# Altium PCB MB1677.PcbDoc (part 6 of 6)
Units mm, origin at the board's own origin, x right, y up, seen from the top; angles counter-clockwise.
Board outline 78 x 105 mm, 6 copper layers (Top Layer, Signal Layer 1, Signal Layer 2, Signal Layer 3, Signal Layer 4, Bottom Layer), stack 1.574 mm thick; 404 components, 325 nets, 1691 pads, 961 vias.
Unrouted connection lines stored in the file: 9.
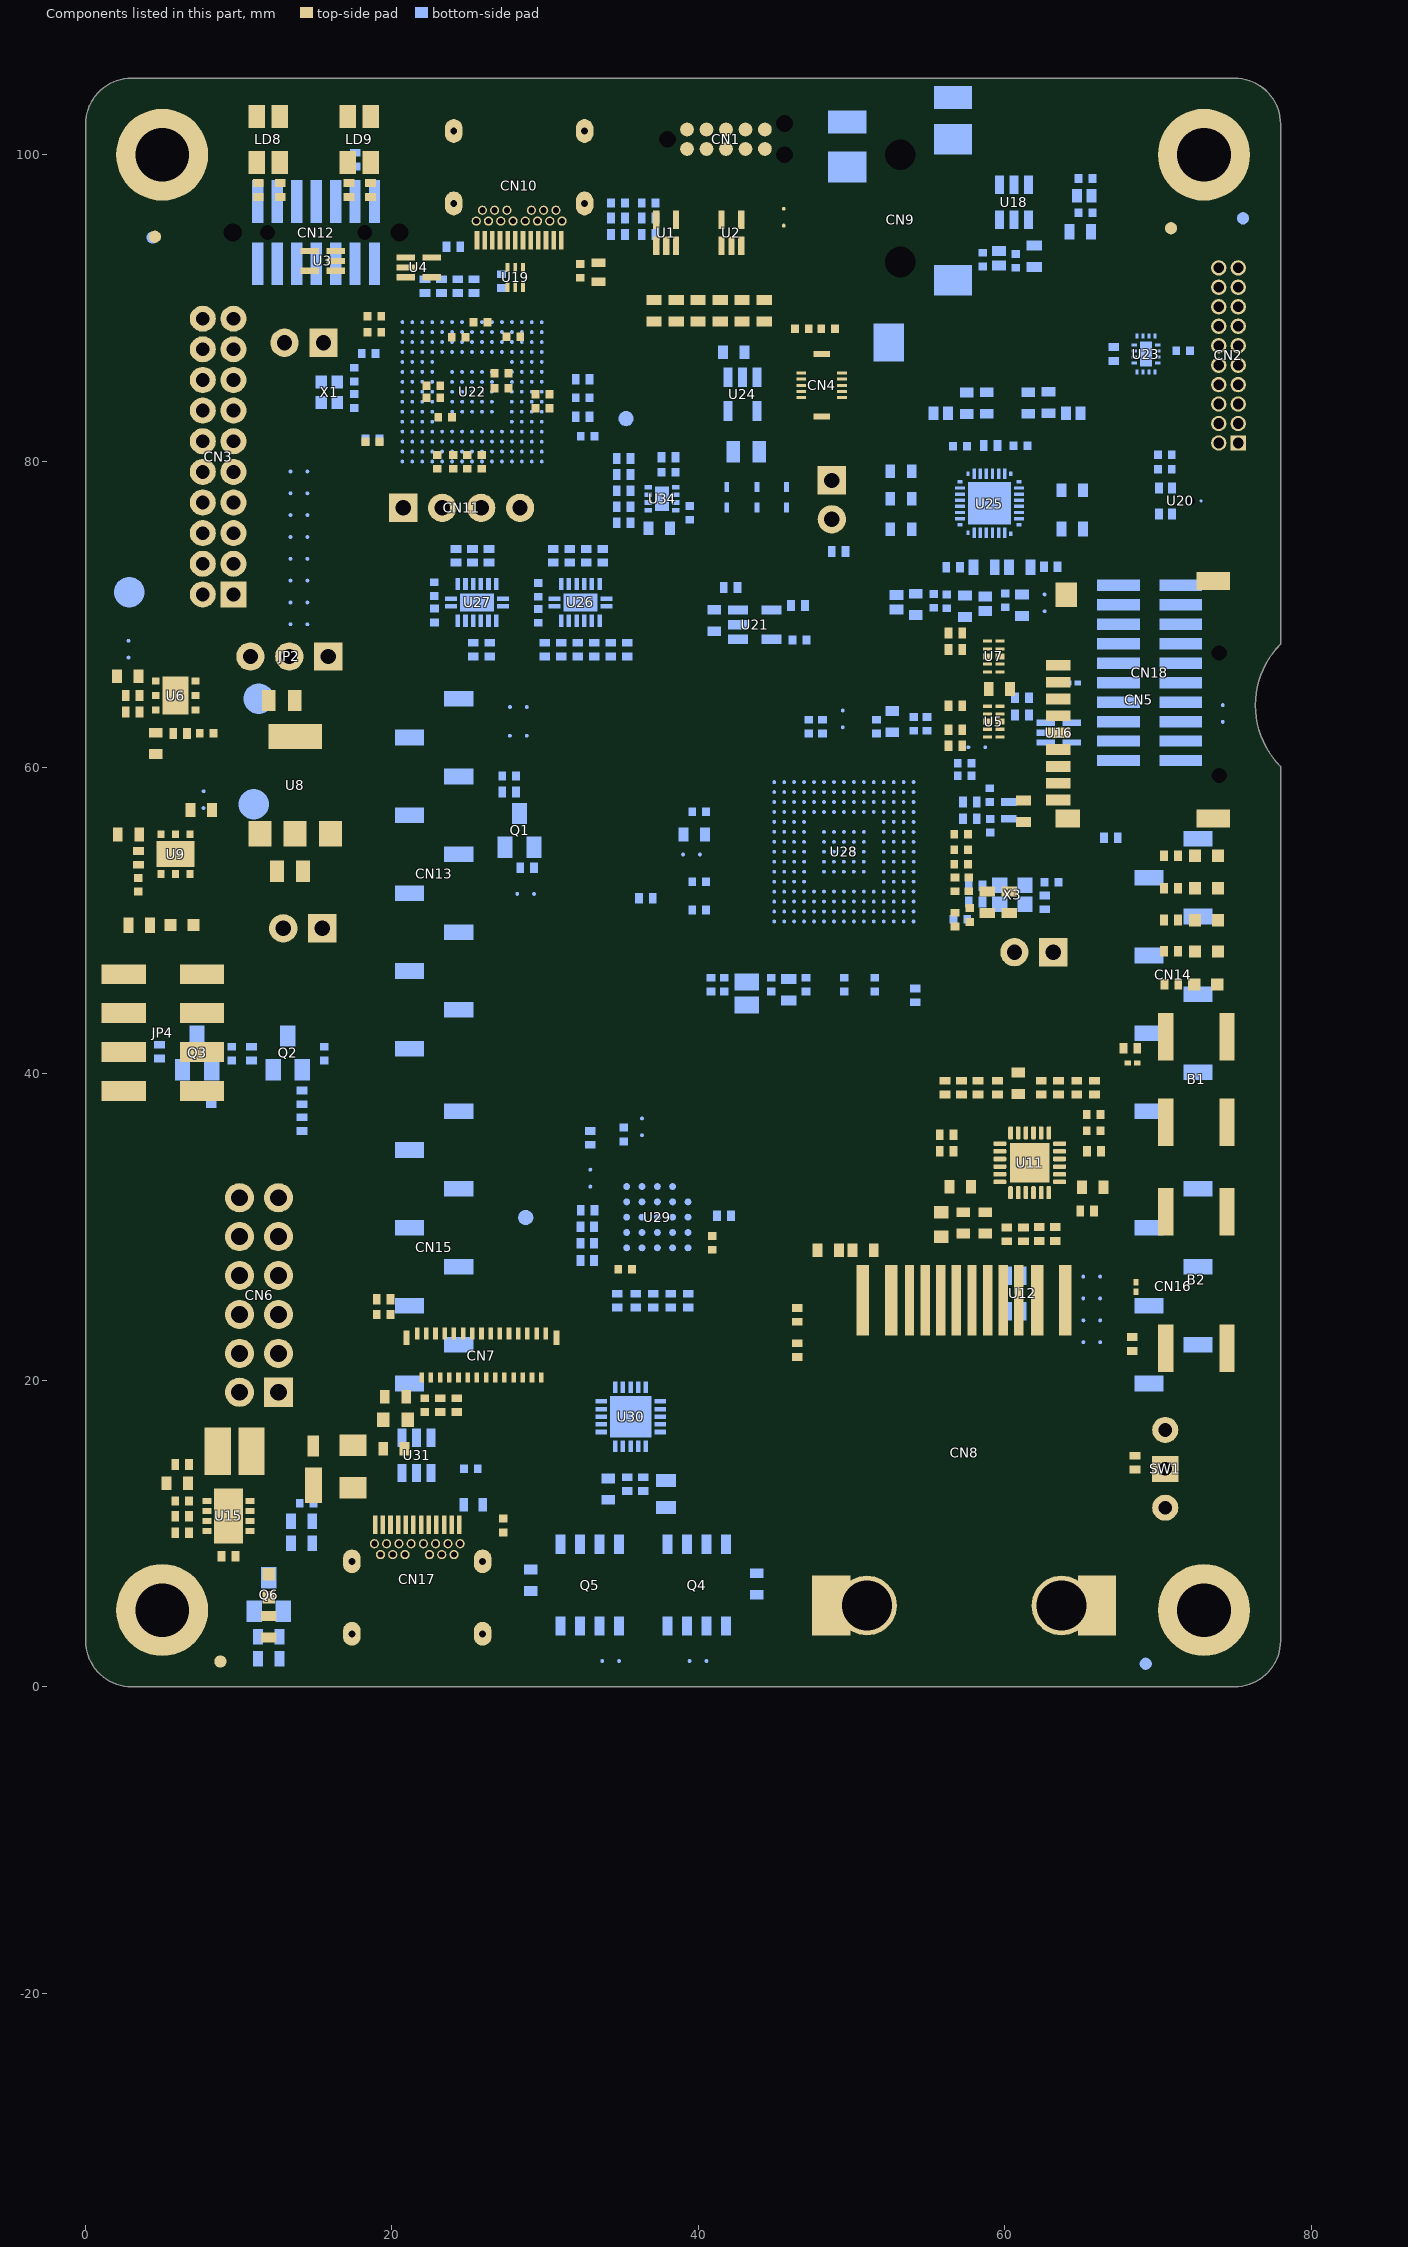
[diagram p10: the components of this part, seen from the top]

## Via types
v1: diameter 0.55, hole 0.35, Top Layer to Bottom Layer, tented both sides, 748 vias
v2: diameter 0.4, hole 0.2, Top Layer to Bottom Layer, tented both sides, 203 vias
v3: diameter 0.6, hole 0.3, Top Layer to Bottom Layer, tented both sides, 9 vias
v4: diameter 0.55, hole 0.33, Top Layer to Bottom Layer, tented both sides, 1 vias

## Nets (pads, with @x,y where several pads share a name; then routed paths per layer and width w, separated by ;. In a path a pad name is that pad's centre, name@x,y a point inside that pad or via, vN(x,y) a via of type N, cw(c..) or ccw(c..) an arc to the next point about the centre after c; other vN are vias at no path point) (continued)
pads on no net: CN1.7 CN1.11 CN1.12 CN1.13 CN2.3 CN2.8 CN2.9 CN2.11 CN2.13 CN2.14 CN2.15 CN2.16 CN2.17 CN2.18 CN4.MT1 CN4.MT2 CN5.NPTH1 CN5.NPTH2 CN6.9 CN6.10 CN7.MT1 CN7.MT2 CN8.9 CN9.5 CN9.7 CN9.MT1 CN9.MT2 CN10.A2 CN10.A3 CN10.A8 CN10.A10 CN10.A11 CN10.B2 CN10.B3 CN10.B8 CN10.B10 CN10.B11 CN12.0 CN12.1 CN12.2 CN17.A2 CN17.A3 CN17.A8 CN17.A10 CN17.A11 CN17.B2 CN17.B3 CN17.B8 CN17.B10 CN17.B11 CN18.7 Designator90.1 Designator91.1 Designator92.1 Designator93.1 Designator94.1 Designator95.1 U1.4 U1.5 U4.4 U7.4 U7.5 U7.6 U7.7 U9.3 U11.4 U15.5 U19.4 U20.6 U22.A1 U22.A2 U22.A3 U22.A4 U22.A5 U22.A8 U22.A9 U22.A11 U22.A12 U22.A13 U22.B1 U22.B2 U22.B3 U22.B4 U22.B5 U22.B6 U22.B7 U22.B8 U22.B9 U22.B10 U22.B11 U22.B12 U22.B14 U22.B15 U22.C2 U22.C3 U22.C4 U22.C12 U22.C13 U22.C14 U22.C15 U22.D1 U22.D2 U22.D3 U22.D11 U22.D13 U22.D14 U22.E1 U22.E2 U22.E3 U22.E4 U22.E12 U22.E13 U22.E14 U22.E15 U22.F1 U22.F4 U22.F14 U22.G4 U22.G14 U22.G15 U22.H2 U22.H3 U22.H4 U22.H14 U22.J2 U22.J3 U22.J4 U22.K1 U22.K2 U22.K3 U22.K12 U22.K13 U22.K14 U22.K15 U22.L1 U22.L12 U22.L13 U22.L14 U22.L15 U22.M2 U22.M3 U22.M4 U22.M7 U22.M12 U22.M13 U22.M14 U22.M15 U22.N2 U22.N4 U22.N6 U22.N7 U22.N11 U22.N13 U22.N14 U22.N15 U22.P2 U22.P4 U22.P5 U22.P6 U22.P7 U22.P8 U22.P9 U22.P10 U22.P11 U22.P12 U22.P13 U22.P14 U22.P15 U22.R2 U22.R6 U22.R7 U22.R8 U22.R9 U22.R10 U22.R11 U22.R12 U22.R13 U23.7 U23.8 U23.9 U23.12 U23.13 U23.14 U23.17 U24.4 U25.16 U25.17 U25.18 U25.24 U25.25 U25.26 U27.3 U27.14 U28.A10 U28.C14 U28.G3 U28.H3 U28.J2 U28.K15 U28.N8 U29.A2 U29.A3 U29.B1 U29.B5 U31.5

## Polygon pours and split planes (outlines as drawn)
GND on Bottom Layer "GND" (solid, remove dead copper, pour order 57): 0.525,107 78.425,107 80.375,105.05 80.375,-0.475 78.4,-2.45 0.025,-2.45 -2.975,0.55 -2.975,103.5
no net on Bottom Layer "NO_FT" (solid, remove dead copper, pour order 8): 48.597,17.325 66.325,17.325 66.325,0 48.697,0 48.597,0.004
5V_STLK on Bottom Layer "5V_STLK" (solid, remove dead copper, pour order 52): 36.475,76.275 36.08,75.88 36.08,75.375 35.85,75.145 35.85,74.65 36,74.5 37.21,74.5 37.347,74.638 37.347,76.004 37.077,76.275
5V_VIN on Bottom Layer "5V_VIN" (solid, pour order 50): 3.6,39.5 4.125,40.025 4.125,41.405 3.675,41.855 3.675,43.734 4.4,44.459 11.159,44.459 14.27,47.57 14.27,50.28 13.469,51.081 12.106,51.081 8.525,47.5 3.45,47.5 1,45.05 1,39.95 1.45,39.5
VBUS_STLK on Bottom Layer "VBUS_STLK" (solid, pour order 47): 42.625,75.075 36.775,69.225 36.775,62.412 36.25,61.888 35.637,61.888 34.85,62.675 34.85,70.565 41.56,77.275 42.3,77.275 42.625,76.95
NetC95_1 on Bottom Layer "NO_FT" (solid, pour order 1): 53.05,60.3 52.625,59.875 52.625,59.05 52.75,59.05 52.875,59.05 52.875,59.425 53.4,59.95
NetC80_2 on Bottom Layer "NO_FT" (solid, pour order 18): 42.7,84.725 43.325,85.35 43.325,86.301 43.479,86.455 44.632,86.455 44.75,86.337 44.75,80.225 45.375,79.6 46.05,79.6 46.55,79.1 46.55,77.975 46.225,77.65 41.475,77.65 41.05,78.075 41.05,79.5 41.225,79.675 42.775,79.675 43.4,80.3 43.4,83.85 43.2,84.05 42.525,84.05 42.4,83.925 42.4,82.525 42.125,82.25 41.275,82.25 40.975,82.55 40.975,84.2 41.5,84.725
NetC125_1 on Bottom Layer "NO_FT" (solid, pour order 6): 38.7,10.975 40,12.275 43.3,12.275 44.9,10.675 44.9,7.375 44.45,6.925 43.4,6.925 43.275,7.05 43.275,8.2 42.95,8.525 41.35,8.525 41.1,8.775 41.1,10.5 40.775,10.825 40.375,10.825 39.95,10.4 39.95,8.75 39.725,8.525 38.95,8.525 38.7,8.775
5V_UCPD on Bottom Layer "NO_FT" (solid, pour order 42): 33.68,2.325 34.075,1.93 34.075,1.43 33.17,0.525 31.65,0.525 31.125,1.05 31.125,2.05 31.4,2.325
5V on Bottom Layer "NO_FT" (solid, pour order 41): 39.455,2.25 39.525,2.18 39.525,1.18 38.87,0.525 37.55,0.525 36.85,1.225 36.85,2.15 36.95,2.25
VIN on Bottom Layer "VIN" (solid, pour order 39): 16.925,54.6 16.225,55.3 15.075,55.3 14.05,54.275 14.05,49.875 15.075,48.85 15.75,48.85 16.925,50.025
VIN on Bottom Layer "NO_FT" (solid, pour order 36): 67.275,41.025 66.55,41.025 66.05,40.525 66.05,38.075 66.225,37.9 67.125,37.9 67.825,38.6 67.825,40.475 67.725,40.575
NetC22_2 on Bottom Layer "NO_FT" (solid, pour order 16): 4.008,67.275 4.197,67.085 4.197,65.622 3.95,65.375 2.55,65.375 2.15,65.775 2.15,67.125 2.3,67.275
3V3 on Bottom Layer "NO_FT" (solid, pour order 13): 7.2,58.7 7.2,59.675 7.825,60.3 9.5,60.3 9.85,59.95 9.85,58.25 9.3,57.7 8.2,57.7
NetC27_2 on Bottom Layer "NO_FT" (solid, pour order 12): 5.65,56.65 5.9,56.4 8.325,56.4 8.45,56.525 8.45,57.2 8.2,57.45 7.025,57.45 6.425,58.05 5.8,58.05 5.65,57.9
NetC124_1 on Bottom Layer "NO_FT" (solid, pour order 7): 35.425,10.525 34.35,11.6 29.475,11.6 28.05,10.175 28.05,7.15 28.25,6.95 29.2,6.95 30.775,8.525 35.2,8.525 35.425,8.75
UCPD_SOURCE on Bottom Layer "NO_FT" (solid, pour order 5): 39.9,7.9 40.225,8.225 42.675,8.225 43.025,7.875 43.025,6.9 43.225,6.7 43.23,6.705 44.47,6.705 44.6,6.575 44.6,3.325 42.275,1 40.45,1 40.35,1.1 40.35,2.625 39.9,3.075
UCPD_SNK03 on Bottom Layer "NO_FT" (solid, pour order 4): 33,7.8 33.15,7.95 35.7,7.95 36.1,7.55 36.1,1.45 35.675,1.025 34.905,1.025 34.6,1.33 34.6,2 34.42,2.18 34.075,2.18 33,3.255
NetC124_2 on Bottom Layer "NO_FT" (solid, pour order 2): 29.05,6.955 29.205,6.955 30.775,8.525 39.575,8.525 39.825,8.275 39.825,3.075 39.55,2.8 37.075,2.8 36.575,3.3 36.575,7.325 35.85,8.05 33.125,8.05 32.925,7.85 32.925,3.125 32.5,2.7 29.35,2.7 27.925,4.125 27.925,6.625 28.25,6.95 28.775,6.95
NetC95_1 on Bottom Layer "NO_FT" (solid, pour order 0): 44.725,48.85 45.475,49.6 45.475,49.95 45.6,50.025 45.725,49.95 45.725,49.15 45.075,48.5
VDD on Signal Layer 3 "VDD" (solid, remove dead copper, pour order 60): 0.525,107 78.425,107 80.375,105.05 80.375,-0.475 78.4,-2.45 0.025,-2.45 -2.975,0.55 -2.975,103.5
1V8 on Signal Layer 3 "1V8" (solid, pour order 19): 25.525,73.325 27.65,71.2 30.825,71.2 31.6,71.95 49.25,71.95 59.1,81.8 63.4,81.8 63.725,81.475 63.725,79.475 57.425,73.175 55.05,73.175 51.3,69.425 12.75,69.425 12.1,68.775 12.1,66.425 11.375,65.7 3.735,65.7 2.942,66.492 2.5,66.935 2.5,69.825 3,70.325 5.375,70.325 6.9,68.8 9.625,68.8 14.15,73.325
3V3_STLK on Signal Layer 3 "3V3_STLK" (solid, remove dead copper, pour order 20): 24.625,89.925 26.825,89.925 30.7,86.05 33.4,86.05 37.3,89.95 39.15,89.95 41.4,87.7 41.4,83.05 44.125,80.325 49.375,80.325 50.675,79.025 50.675,73.775 49.025,72.125 33.717,72.125 31.97,73.872 31.005,73.872 27.245,73.872 25.842,75.275 19.7,75.275 18.9,76.075 18.9,80.45 18.425,80.925 17.2,80.925 16.775,81.35 16.775,84.95 19.2,87.375 19.2,89.4 19.725,89.925
5V on Signal Layer 3 "5V" (solid, pour order 37): 13.725,6.675 34.3,6.675 43.4,6.675 52.995,16.27 74.205,16.27 76.55,13.925 76.55,12.85 75.9,12.2 51.875,12.2 40.2,0.525 12.525,0.525 12.525,5.475
3V3_LCD on Signal Layer 3 "3V3_LCD" (solid, pour order 33): 22.008,96.6 18.208,100.4 11.925,100.4 11.275,99.75 11.275,98.15 6.275,93.15 1.775,93.15 1.444,92.819 1.444,44.731 2.95,43.225 9.55,43.225 10.075,42.7 10.075,41.75 9.925,41.6 1.775,41.6 0.5,42.875 0.5,93.35 1.8,94.65 5.425,94.65 9.2,98.425 9.2,100.325 10.9,102.025 20.5,102.025 24.1,98.425 27.875,94.65 44.475,94.65 48.535,90.59 48.535,88.953 48.359,88.778 47.788,88.778 47.625,88.94 47.625,89.725 45.35,92 26.608,92
VBUSC on Signal Layer 3 "VBUSC" (solid, pour order 23): 14.575,6.925 25.425,6.925 25.425,9.825 27.175,11.575 36.6,11.575 36.975,11.95 36.975,15.15 37.725,15.9 38.325,15.9 38.8,16.375 38.8,16.95 38.5,17.25 37.2,17.25 33.625,13.675 24.766,13.675 23.118,12.028 14.028,12.028 10.475,8.475 10.475,4.775 9.55,3.85 9.55,0.5 12.275,0.5 12.275,5.658 13.542,6.925
VBUS_STLK on Signal Layer 3 "VBUS_STLK" (solid, pour order 49): 28.6,41.9 30.425,41.9 33.667,45.142 35.91,45.142 36.342,45.142 36.848,44.637 37.188,44.637 38.2,43.624 38.2,38.5 19.525,38.5 19.025,38 5.725,38 4.644,36.919 3.448,36.919 3.275,37.092 3.275,39.015 3.939,39.679 10.929,39.679 13.15,41.9
5V_UCPD on Signal Layer 3 "5V_UCPD" (solid, pour order 40): 32.625,47.225 30.6,45.2 4.3,45.2 3.925,45.575 3.35,45.575 3.075,45.3 3.075,44.501 4.226,43.35 15.7,43.35 16.975,42.075 30.075,42.075 33.142,45.142 36.342,45.142 36.848,44.637 37.188,44.637 37.465,44.359 37.465,43.985 37.725,43.725 38,43.725 38.575,44.3 38.575,45.1 36.45,47.225
5V on Signal Layer 3 "5V" (solid, remove dead copper, pour order 59): 13.577,37.75 14.576,36.751 15.267,36.751 15.465,36.553 15.465,34.14 14.55,33.225 2.575,33.225 1.925,33.875 1.925,35.8 2.678,36.553 4.778,36.553 5.975,37.75
5V_STLK on Signal Layer 3 "5V_STLK" (solid, remove dead copper, pour order 54): 30.708,45.933 30.708,47.717 30.325,48.1 4.25,48.1 3.75,47.6 3.75,46.183 4.483,45.45 30.225,45.45
VIN on Signal Layer 3 "VIN" (solid, pour order 35): 63.075,37.65 66.5,41.075 67.325,41.075 67.45,40.95 67.45,38.31 67.103,37.963 65.828,37.963 63.865,36 52.2,36 48.825,32.625 43.35,32.625 38.5,37.475 38.5,45.475 36.5,47.475 31.084,47.475 30.359,48.2 18.55,48.2 14.75,52 14.75,53.885 15.915,55.05 19.5,55.05 24.65,49.9 38.625,49.9 40.609,47.916 40.609,38.616 43.597,35.628 47.112,35.628 50.309,38.825 59.05,38.825 60.225,37.65
VDD_MCU on Signal Layer 3 "VDD_MCU" (solid, pour order 45): 49.137,65.862 49.137,64.137 47.65,62.65 43.875,62.65 40.25,59.025 40.25,50.6 41.3,49.55 41.3,47.1 44.75,43.65 48.675,43.65 51.375,46.35 52.75,46.35 53.775,47.375 53.775,50.65 54.725,51.6 58,51.6 58.275,51.325 58.275,47.475 59.55,46.2 61.45,46.2 61.975,46.725 61.975,50.475 59.425,53.025 59.425,60.2 59.825,60.6 59.825,61.25 58.3,62.775 55.9,62.775 55.225,63.45 55.225,65.45 54.6,66.075 49.35,66.075
NetC40_1 on Signal Layer 3 "NO_FT" (solid, pour order 9): 62.575,32.15 63.25,32.825 64.05,32.825 64.625,32.25 64.625,28.45 62.85,26.675 45.875,26.675 45.625,26.925 45.625,27.6 47.05,29.025 57.1,29.025 58.975,30.9 58.975,31.925 59.2,32.15
NetC95_1 on Signal Layer 3 "NO_FT" (solid, pour order 24): 46.05,49.4 45.525,49.925 41.425,49.925 40.75,50.6 40.75,59.05 44.05,62.35 52.875,62.35 53.225,62 53.225,60.774 52.591,60.14 52.591,59.859 53.1,59.35 53.6,59.35 54.65,60.4 54.65,62.275 53.367,63.558 43.683,63.558 39.4,59.275 39.4,49.95 41.05,48.3 45.775,48.3 46.05,48.575
NetC124_2 on Signal Layer 3 "NO_FT" (solid, pour order 3): 37.5,11.6 35.975,10.075 35.975,7.825 36.225,7.575 37.85,7.575 38.4,8.125 38.4,14.775 38.225,14.95 37.625,14.95 37.5,14.825
GND on Top Layer "GND" (solid, remove dead copper, pour order 43): 0.525,107 78.425,107 80.375,105.05 80.375,-0.475 78.4,-2.45 0.025,-2.45 -2.975,0.55 -2.975,103.5
5V on Top Layer "NO_FT" (solid, pour order 26): 5.425,46.5 4.425,47.5 2.625,47.5 1.4,48.725 1.4,50.175 1.9,50.675 3.175,50.675 3.675,50.175 3.675,48.625 4.1,48.2 9.725,48.2 11.125,46.8 11.125,36.05 10.625,35.55 6,35.55 5.425,36.125
5V_VIN on Top Layer "NO_FT" (solid, pour order 31): 0.85,42.275 0.85,40.024 1.149,39.725 3.625,39.725 4.15,40.25 4.15,42.275
VIN on Top Layer "NO_FT" (solid, pour order 25): 15,54.95 14.275,54.225 13.8,54.225 13.35,53.775 13.35,52.275 13.825,51.8 15.75,51.8 16.2,52.25 16.2,53.825 17.2,54.825 17.2,56.425 16.8,56.825 15.3,56.825 15,56.525
NetC22_2 on Top Layer "NO_FT" (solid, pour order 15): 4.95,66.325 4,67.275 3.075,67.275 2.5,66.7 2.5,65.625 2.975,65.15 4.775,65.15 4.95,65.325
3V3 on Top Layer "NO_FT" (solid, pour order 14): 2.575,62.625 2.45,62.5 2.45,61.75 2.7,61.5 5.875,61.5 6.175,61.8 6.175,62.75 5.75,63.175 5.25,63.175 4.95,63.475 4.95,64.05 4.8,64.2 4.2,64.2 4,63.975 4,62.725 3.9,62.625
NetC27_2 on Top Layer "NO_FT" (solid, pour order 11): 5.525,57.725 5.725,57.925 6.85,57.925 7.55,57.225 7.55,55.725 7.05,55.225 5.725,55.225 5.525,55.425
5V on Top Layer "NO_FT" (solid, pour order 10): 2.675,56.7 2.875,56.9 5.025,56.9 5.45,56.475 5.45,55.5 5.175,55.225 4.625,55.225 4.075,54.675 4.075,54.15 4.025,54.1 2.95,54.1 2.675,54.375
GND on Signal Layer 2 "GND" (solid, remove dead copper, pour order 58): 0.525,107 78.425,107 80.375,105.05 80.375,-0.475 78.4,-2.45 0.025,-2.45 -2.975,0.55 -2.975,103.5
VBUS_STLK on Signal Layer 2 "VBUS_STLK" (solid, pour order 46): 25.021,96.85 25.021,97.521 26,98.5 34.175,98.5 36.275,96.4 37.45,95.225 37.45,93.875 43.55,87.775 43.55,76.55 46.625,73.475 46.625,68.915 46.36,68.65 45.075,68.65 44.275,69.45 44.275,71.325 41.025,74.575 39.997,75.603 39.997,83.253 37.475,85.775 37.475,88.975 35.45,91 33.5,91 31.875,92.625 26.675,92.625 25.021,94.279
5V_UCPD on Signal Layer 2 "5V_UCPD" (solid, pour order 51): 35.95,45.95 36.575,46.575 37.382,46.575 39.625,44.284 39.625,31.955 32.775,25.105 32.775,13.95 33.425,13.3 33.425,0.942 33.008,0.525 31.925,0.525 30.55,1.9 30.55,28.025 35.95,33.425
5V on Signal Layer 2 "5V" (solid, pour order 29): 3.15,60.125 4,59.275 4,44.224 4.65,43.574 4.65,15.1 13.263,6.487 14.603,6.487 14.783,6.308 14.783,5.208 14.375,4.8 9.425,4.8 1.025,13.2 1.025,92.2 1.85,93.025 5.575,93.025 5.975,92.625 5.975,78.875 3.15,76.05
3V3_STLK on Signal Layer 2 "3V3_STLK" (solid, remove dead copper, pour order 53): 21.4,88.35 21.5,88.45 21.5,90.9 18.875,93.525 18,93.525 17.7,93.825 17.7,103.675 17.308,104.067 11.023,104.067 10.825,103.869 10.825,103.325 12.75,101.4 14.725,101.4 15.825,100.3 15.825,93.3 18.4,90.725 19.175,90.725 19.175,88.525 19.35,88.35
VBUS_STLK on Signal Layer 2 "VBUS_STLK" (solid, pour order 48): 34.187,64.062 34.187,60.591 32.65,59.054 32.65,58.602 32.65,54.679 31.85,53.879 31.85,45.85 34.712,42.987 36.263,42.988 37.025,43.75 37.025,44.125 33.825,47.325 33.825,53.65 34.8,54.625 34.8,57.925 36.8,59.925 36.8,64.75 36.45,65.1 35.225,65.1
5V_STLK on Signal Layer 2 "5V_STLK" (solid, remove dead copper, pour order 56): 33.925,64.233 33.925,60.7 32.475,59.25 32.475,58.879 32.475,54.975 31.525,54.025 31.525,46.75 30.7,45.925 28.307,45.925 27.8,46.432 27.8,59.65 30.316,62.166 30.316,64.991 34.3,68.975 34.3,75.45 34.7,75.85 37.15,75.85 37.6,75.4 37.6,74.125 41.025,70.7 41.025,69 37.425,65.4 35.092,65.4
5V on Signal Layer 2 "5V" (solid, pour order 38): 73.775,45.825 73.775,42.875 74.65,42 74.65,12.95 75.225,12.375 76.125,12.375 76.875,13.125 76.875,44.725 75.375,46.225 74.175,46.225
GND on Signal Layer 1 "GND" (solid, remove dead copper, pour order 30): 0.525,107 78.425,107 80.375,105.05 80.375,-0.475 78.4,-2.45 0.025,-2.45 -2.975,0.55 -2.975,103.5
3V3 on Signal Layer 4 "3V3" (solid, remove dead copper, pour order 34): 2.125,106.375 80.025,106.375 81.975,104.425 81.975,-1.1 80,-3.075 1.625,-3.075 -1.375,-0.075 -1.375,102.875

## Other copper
Top Layer:
  text "1" at 60.368,102.478 h2
  text ".Layer_Name" at -1.072,-25.883 h3
  text ".GTL" at 40.623,-25.883 h3
Signal Layer 1:
  text "2" at 61.618,102.478 h2
  text ".Layer_Name" at -1.072,-25.883 h3
  text ".G1" at 40.623,-25.883 h3
Signal Layer 2:
  text "3" at 63.118,102.478 h2
  text ".Layer_Name" at -1.072,-25.883 h3
  text ".G2" at 40.623,-25.883 h3
Signal Layer 3:
  text "4" at 65.368,102.478 h2
  text ".Layer_Name" at -1.04,-25.866 h3
  text ".G3" at 40.655,-25.866 h3
Signal Layer 4:
  text "5" at 66.868,102.478 h2
  text ".Layer_Name" at -1.04,-25.866 h3
  text ".G4" at 40.655,-25.866 h3
Bottom Layer:
  text "6" at 68.368,102.478 h2
  text ".GBL" at 29.42,-25.915 h3
  text ".Layer_Name" at 70.734,-25.915 h3
Multi-Layer:
  pour cut-out: 60.075,104.05 60.075,102.075 68.575,102.075 68.575,104.05

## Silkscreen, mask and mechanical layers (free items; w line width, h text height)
Top Overlay:
  lines w0.1: 69.595,75.975 69.595,78.725 73.195,78.725 73.195,75.975 69.595,75.975
  lines w0.12: 74.175,11.125 74.175,11.7 ; 74.175,12.15 74.175,12.725 ; 74.175,13.175 74.175,13.75 ; 74.175,14.2 74.175,14.775 ; 74.175,15.225 74.175,15.8 ; 74.175,16.25 74.175,16.825 ; 0.55,13.125 2.05,13.125 2.05,16.9 0.55,16.9 0.55,13.125 ; 0.975,91.125 2.475,91.125 2.475,96 0.975,96 0.975,91.125 ; 14.408,45.643 16.8,45.643 16.8,46.875 14.408,46.875 14.408,45.643 ; 19.43,75.65 19.43,78.25 29.66,78.25 29.67,78.24 29.67,75.65 19.43,75.65 ; 21.425,96.975 21.425,104.1 22.775,104.1 22.775,96.975 21.425,96.975 ; 26.7,12 26.7,19.15 29.075,19.15 29.075,12 26.7,12 ; 28.325,0.75 29.825,0.75 29.825,4.525 28.325,4.525 28.325,0.75 ; 46.6,13.1 48.1,13.1 48.1,19.375 46.6,19.375 46.6,13.1 ; 48.6,101.15 49.825,101.15 49.825,103.675 48.6,103.675 48.6,101.15 ; 51.05,82.3 52.85,82.3 52.85,87.875 51.05,87.875 51.05,82.3 ; 70.9,88.05 72.4,88.05 72.4,92.975 70.9,92.975 70.9,88.05 ; 74.925,12.05 74.925,16.225 76.425,16.225 76.425,12.05 74.925,12.05 ; 75.825,72.675 75.825,75.65 77.325,75.65 77.325,72.675 75.825,72.675 ; 76.118,37.892 76.118,41.417 77.618,41.417 77.618,37.892 76.118,37.892 ; 76.145,24.637 76.145,28.65 77.645,28.65 77.645,24.637 76.145,24.637
  text "TAG" at 49.6,101.325 h1.2 r90
  text "STLK_COM" at 16.125,98.675 h1.2 r90
  text "STLK_PWR" at 10.2,98.45 h1.2 r90
  text "USB_STLINK" at 22.65,97.35 h1.2 r90
  text "STMOD+" at 2.15,91.4 h1.2 r90
  text "EXT_MIC" at 72.175,88.3 h1.2 r90
  text "MIC" at 74.4,76.3 h1.3 r90
  text "RESERVED" at 21.775,74.5 h1.2
  text "µSD" at 77.15,73.175 h1.2 r90
  text "1V8" at 9.925,68.8 h1.2
  text "VDD" at 12.275,68.8 h1.2
  text "3V3" at 14.925,68.8 h1.2
  text "STLK" at 9.5,46.125 h1.2
  text "VIN" at 14.7,45.85 h1.2
  text "USB-PD" at 9.525,43.575 h1.2
  text "5VIN" at 9.425,41 h1.2
  text "CHGR" at 9.4,38.575 h1.2
  text "USER" at 77.293,38.166 h1.2 r90
  text "RESET" at 77.32,24.912 h1.2 r90
  text "K" at 39.625,17.3 h11.5 r90
  text "1" at 74.425,17.2 h1.2 r90
  text "SYS/MEM" at 73.45,15.05 h1.2 r90
  text "DISPLAY" at 27.875,14.575 h1.2 r90
  text "PMOD" at 1.725,13.425 h1.2 r90
  text "ETHERNET" at 47.775,13.4 h1.2 r90
  text "BOOT0" at 76.1,12.4 h1.2 r90
  text "CONNECTOR" at 28.875,12.2 h1.2 r90
  text "0" at 74.55,10.35 h1.2 r90
  text "FLASH" at 73.5,9.025 h1.2 r90
  text "MB1677D" at 42.65,1.925 h3 r90
  text "J" at 40.9,1.3 h20 r90
  text "USB-C" at 29.5,1.05 h1.2 r90
  text ".Layer_Name" at -1.072,-25.883 h3
  text ".GTO" at 40.623,-25.883 h3
Bottom Overlay:
  lines w0.12: 21.8,92.425 25.1,92.425 ; 25.125,92.45 25.825,93.15 ; 25.35,93.15 29.125,93.15 ; 12.725,89.3 15.9,89.3 15.9,90.525 12.725,90.525 12.725,89.3 ; 13.15,99.175 13.15,100.4 16.75,100.4 16.75,99.175 13.15,99.175 ; 48.15,90.575 48.15,94.3 49.375,94.3 49.375,90.575 48.15,90.575 ; 60.85,44.975 63.2,44.975 63.2,46.2 60.85,46.2 60.85,44.975 ; 64.125,68.35 65.35,68.35 65.35,72.25 64.125,72.25 64.125,68.35
  text "MIPI10" at 16.575,99.4 h1.2
  text "E" at 44.8,98.25 h10 r90
  text "AUDIO" at 49.15,94.125 h1.2 r90
  text "NRST" at 15.725,89.525 h1.2
  text "TRACE" at 65.125,72.075 h1.2 r90
  text "D15/SCL" at 19.5,64.175 h1.2
  text "D14/SDA" at 19.5,61.525 h1.2
  text "AVDD" at 19.5,59.075 h1.2
  text "GND" at 19.5,56.475 h1.2
  text "NC" at 75.7,54.975 h1.2
  text "D13/SCK" at 19.5,53.925 h1.2
  text "I" at 7.675,53.075 h10 r90
  text "IOREF" at 77.45,52.5 h1.2
  text "D12/MISO" at 19.5,51.425 h1.2
  text "NRST" at 77.15,49.9 h1.2
  text "D11" at 19.5,49.625 h1.2
  text "PWM" at 19.5,48.775 h1.2
  text "MOSI" at 19.5,47.9 h1.2
  text "3V3" at 76.125,47.4 h1.2
  text "D10/PWM/CS" at 19.5,46.325 h1.2
  text "IDD" at 62.85,45.2 h1.2
  text "5V" at 75.575,44.85 h1.2
  text "H" at 66,44.1 h20 r90
  text "D9/PWM" at 19.5,43.725 h1.2
  text "GND" at 76.525,42.35 h1.2
  text "D8" at 19.5,41.275 h1.2
  text "GND" at 76.55,39.725 h1.2
  text "F" at 5.9,37.6 h11 r90
  text "D7" at 19.5,37.3 h1.2
  text "VIN" at 75.975,37.125 h1.2
  text "C" at 53.1,35.75 h9 r90
  text "D6/PWM" at 19.5,34.65 h1.2
  text "D5/PWM" at 19.5,32.15 h1.2
  text "A0" at 75.525,32.125 h1.2
  text "A1" at 75.525,29.6 h1.2
  text "D4" at 19.5,29.55 h1.2
  text "D3/PWM" at 19.5,27.075 h1.2
  text "A2" at 75.525,27 h1.2
  text "G" at 5.9,26.825 h10 r90
  text "A3" at 75.525,24.525 h1.2
  text "D2" at 19.5,24.475 h1.2
  text "D1/TX" at 19.5,21.95 h1.2
  text "A4" at 75.525,21.95 h1.2
  text "D0/RX" at 19.5,19.4 h1.2
  text "A5" at 75.525,19.375 h1.2
  text "S" at 5.9,15.05 h7.5 r90
  text ".GBO" at 29.42,-25.915 h3
  text ".Layer_Name" at 70.734,-25.915 h3
Top Paste:
  text ".Layer_Name" at -1.099,-25.873 h3
  text ".GTP" at 40.596,-25.873 h3
Bottom Paste:
  text ".GBP" at 29.311,-25.9 h3
  text ".Layer_Name" at 70.625,-25.9 h3
Top Solder:
  rectangle: 60.075,102.075 68.575,104.05
  text ".Layer_Name" at -1.074,-25.948 h3
  text ".GTS" at 40.621,-25.948 h3
Bottom Solder:
  rectangle: 60.075,102.075 68.575,104.075
  text ".GBS" at 29.336,-25.975 h3
  text ".Layer_Name" at 70.65,-25.975 h3
M1-Board Shape:
  the board outline again, w0.1
M2-Board Dimensions:
  text ".Layer_Name" at -1.072,-25.883 h3
  text ".GM2" at 40.623,-25.883 h3
M14-Top Assembly:
  text ".Layer_Name" at -1.072,-25.883 h3
  text ".GM14" at 40.623,-25.883 h3
M15-Bottom Assembly:
  text ".GM15" at 29.42,-25.915 h3
  text ".Layer_Name" at 70.734,-25.915 h3
Drill Drawing:
  drawing of 525 lines, arcs and shapes, not listed
  text "PCB SPECIFICATIONS :" at -10.3,155.854 h3
  text "PCB : TYPE 3" at 138.112,155.622 h3
  text "A.   MATERIAL :" at -10.3,151.854 h3
  text "FR-4" at 28.2,151.854 h3
  text "TG-170" at 44.7,151.854 h3
  text "X  TG-150" at 62.95,151.854 h3
  text "TG-140" at 78.95,151.854 h3
  text "ASPECT-RATIO, AXE Z :" at 138.112,150.122 h3
  text "B.   MATERIAL FAMILY :" at -10.3,148.854 h3
  text "N/A" at 28.2,148.854 h3
  text "C.   SOLDERMASK COLOR :" at -10.3,145.854 h3
  text "GREEN" at 28.2,145.854 h3
  text "WHITE" at 44.7,145.854 h3
  text "X  BLUE" at 62.95,145.854 h3
  text "BLACK" at 78.95,145.854 h3
  text "6:1 to 8:1 / LEVEL \"B\"" at 138.13,143.374 h3
  text "D.   SILKSCREEN COLOR :" at -10.3,142.854 h3
  text "X  WHITE" at 28.2,142.854 h3
  text "YELLOW" at 44.7,142.854 h3
  text "BLACK" at 62.95,142.854 h3
  text "Blue ink PANTONE 2955" at 78.95,142.854 h3
  text "E.   SURFACE FINISH :" at -10.3,139.854 h3
  text "X  ENIG" at 28.2,139.854 h3
  text "IMMERSION SILVER" at 44.7,139.854 h3
  text "IMMERSION TIN" at 78.95,139.854 h3
  text "MINIMUM PARAMETERS" at 138.157,137.773 h3
  text "HASL" at 28.2,136.854 h3
  text "HASL (PB-FREE)" at 44.7,136.854 h3
  text "GOLDEN FINGER" at 78.95,136.854 h3
  text "F.   IMPEDANCE CONTROL :" at -10.3,133.854 h3
  text "NO" at 28.2,133.854 h3
  text "X  YES  (SEE IMPEDANCE TABLE FOR DETAIL INFORMATION)" at 44.7,133.854 h3
  text "DEFAULT" at 138.157,132.273 h3
  text "G.   THROUGH VIA :" at -10.3,130.854 h3
  text "PLUG THE VIAS WHICH ARE COVERED WITH SOLDERMASK ONE OR TWO SIDE." at 28.2,130.854 h3
  text "PLUG MATERIAL :" at 28.2,127.854 h3
  text "X  SOLDERMASK" at 53.7,127.854 h3
  text "NON-CONDUCTIVE EPOXY." at 78.95,127.854 h3
  text "TRACKS : 0.1mm           / GAPS : 0.09mm" at 138.157,126.523 h3
  text "H.   STACK-UP :" at -10.3,124.854 h3
  text "SEE LAYER STACK-UP SEQUENCE FOR OVERALL THICKNESS." at 28.2,124.854 h3
  text "Layer" at 101.554,115.544 h1.52
  text "Name" at 107.932,115.544 h1.52
  text "Material" at 120.266,115.544 h1.52
  text "Thickness" at 131.349,115.544 h1.52
  text "Constant" at 140.453,115.544 h1.52
  text "Board Layer Stack" at 148.879,115.544 h1.52
  text "Top Overlay" at 107.932,112.496 h1.52
  text "Top Solder" at 107.932,109.448 h1.52
  text "Solder Resist" at 120.266,109.448 h1.52
  text "0,015mm" at 131.349,109.448 h1.52
  text "3.5" at 140.453,109.448 h1.52
  text "1" at 101.554,106.4 h1.52
  text "Top Layer" at 107.932,106.4 h1.52
  text "0,042mm" at 131.349,106.4 h1.52
  text "Dielectric 1" at 107.932,103.352 h1.52
  text "0,100mm" at 131.349,103.352 h1.52
  text "4.2" at 140.453,103.352 h1.52
  text "2" at 101.553,100.304 h1.52
  text "Signal Layer 1" at 107.932,100.304 h1.52
  text "0,035mm" at 131.349,100.304 h1.52
  text "Dielectric 2" at 107.932,97.256 h1.52
  text "0,102mm" at 131.349,97.256 h1.52
  text "4.2" at 140.453,97.256 h1.52
  text "3" at 101.554,94.208 h1.52
  text "Signal Layer 2" at 107.932,94.208 h1.52
  text "0,035mm" at 131.349,94.208 h1.52
  text "Dielectric 3" at 107.932,91.16 h1.52
  text "0,946mm" at 131.349,91.16 h1.52
  text "4.2" at 140.453,91.16 h1.52
  text "4" at 101.554,88.112 h1.52
  text "Signal Layer 3" at 107.932,88.112 h1.52
  text "0,035mm" at 131.349,88.112 h1.52
  text "Dielectric 4" at 107.932,85.064 h1.52
  text "0,102mm" at 131.349,85.064 h1.52
  text "4.2" at 140.453,85.064 h1.52
  text "5" at 101.554,82.016 h1.52
  text "Signal Layer 4" at 107.932,82.016 h1.52
  text "0,035mm" at 131.349,82.016 h1.52
  text "Dielectric 5" at 107.932,78.968 h1.52
  text "0,100mm" at 131.349,78.968 h1.52
  text "4.2" at 140.453,78.968 h1.52
  text "6" at 101.554,75.92 h1.52
  text "Bottom Layer" at 107.932,75.92 h1.52
  text "0,042mm" at 131.349,75.92 h1.52
  text "Bottom Solder" at 107.932,72.872 h1.52
  text "Solder Resist" at 120.266,72.872 h1.52
  text "0,015mm" at 131.349,72.872 h1.52
  text "3.5" at 140.453,72.872 h1.52
  text "Bottom Overlay" at 107.932,69.824 h1.52
  text "Symbol" at 102.383,59.08 h1.83
  text "Count" at 109.543,59.08 h1.83
  text "Hole Size" at 117.637,59.08 h1.83
  text "Plated" at 132.308,59.08 h1.83
  text "Hole Type" at 138.594,59.08 h1.83
  text "Drill Layer Pair" at 147.745,59.08 h1.83
  text "Via/Pad" at 165.088,59.08 h1.83
  text "1" at 109.543,55.926 h1.52
  text "0,330mm (12,99mil)" at 117.637,55.926 h1.52
  text "PTH" at 132.308,55.926 h1.52
  text "Round" at 138.594,55.926 h1.52
  text "Top Layer - Bottom Layer" at 147.745,55.926 h1.52
  text "Via" at 165.088,55.926 h1.52
  text "1" at 109.543,52.771 h1.52
  text "0,500mm (19,69mil)" at 117.637,52.771 h1.52
  text "NPTH" at 132.308,52.771 h1.52
  text "Round" at 138.594,52.771 h1.52
  text "Top Layer - Bottom Layer" at 147.745,52.771 h1.52
  text "Pad" at 165.088,52.771 h1.52
  text "2" at 109.543,49.617 h1.52
  text "0,450mm (17,72mil)" at 117.637,49.617 h1.52
  text "PTH" at 132.308,49.617 h1.52
  text "Slot" at 138.594,49.617 h1.52
  text "Top Layer - Bottom Layer" at 147.745,49.617 h1.52
  text "Pad" at 165.088,49.617 h1.52
  text "2" at 109.543,46.463 h1.52
  text "0,970mm (38,19mil)" at 117.637,46.463 h1.52
  text "NPTH" at 132.308,46.463 h1.52
  text "Round" at 138.594,46.463 h1.52
  text "Top Layer - Bottom Layer" at 147.745,46.463 h1.52
  text "Pad" at 165.088,46.463 h1.52
  text "2" at 109.543,43.309 h1.52
  text "1,000mm (39,37mil)" at 117.637,43.309 h1.52
  text "NPTH" at 132.308,43.309 h1.52
  text "Round" at 138.594,43.309 h1.52
  text "Top Layer - Bottom Layer" at 147.745,43.309 h1.52
  text "Pad" at 165.088,43.309 h1.52
  text "G" at 101.741,43.055 h1.4
  text "2" at 109.543,40.155 h1.52
  text "1,190mm (46,85mil)" at 117.637,40.155 h1.52
  text "NPTH" at 132.308,40.155 h1.52
  text "Round" at 138.594,40.155 h1.52
  text "Top Layer - Bottom Layer" at 147.745,40.155 h1.52
  text "Pad" at 165.088,40.155 h1.52
  text "2" at 109.543,37 h1.52
  text "2,000mm (78,74mil)" at 117.637,37 h1.52
  text "NPTH" at 132.308,37 h1.52
  text "Round" at 138.594,37 h1.52
  text "Top Layer - Bottom Layer" at 147.745,37 h1.52
  text "Pad" at 165.088,37 h1.52
  text "D" at 101.741,36.747 h1.4
  text "2" at 109.543,33.846 h1.52
  text "3,250mm (127,95mil)" at 117.637,33.846 h1.52
  text "PTH" at 132.308,33.846 h1.52
  text "Round" at 138.594,33.846 h1.52
  text "Top Layer - Bottom Layer" at 147.745,33.846 h1.52
  text "Pad" at 165.088,33.846 h1.52
  text "3" at 109.543,30.692 h1.52
  text "1,100mm (43,31mil)" at 117.637,30.692 h1.52
  text "NPTH" at 132.308,30.692 h1.52
  text "Round" at 138.594,30.692 h1.52
  text "Top Layer - Bottom Layer" at 147.745,30.692 h1.52
  text "Pad" at 165.088,30.692 h1.52
  text "4" at 109.543,27.538 h1.52
  text "3,500mm (137,79mil)" at 117.637,27.538 h1.52
  text "PTH" at 132.308,27.538 h1.52
  text "Round" at 138.594,27.538 h1.52
  text "Top Layer - Bottom Layer" at 147.745,27.538 h1.52
  text "Pad" at 165.088,27.538 h1.52
  text "6" at 109.543,24.384 h1.52
  text "0,450mm (17,72mil)" at 117.637,24.384 h1.52
  text "PTH" at 132.308,24.384 h1.52
  text "Slot" at 138.594,24.384 h1.52
  text "Top Layer - Bottom Layer" at 147.745,24.384 h1.52
  text "Pad" at 165.088,24.384 h1.52
  text "9" at 109.543,21.229 h1.52
  text "0,300mm (11,81mil)" at 117.637,21.229 h1.52
  text "PTH" at 132.308,21.229 h1.52
  text "Round" at 138.594,21.229 h1.52
  text "Top Layer - Bottom Layer" at 147.745,21.229 h1.52
  text "Via" at 165.088,21.229 h1.52
  text "12" at 109.543,18.075 h1.52
  text "1,100mm (43,31mil)" at 117.637,18.075 h1.52
  text "PTH" at 132.308,18.075 h1.52
  text "Round" at 138.594,18.075 h1.52
  text "Top Layer - Bottom Layer" at 147.745,18.075 h1.52
  text "Pad" at 165.088,18.075 h1.52
  text "E" at 101.741,17.821 h1.4
  text "15" at 109.543,14.921 h1.52
  text "1,000mm (39,37mil)" at 117.637,14.921 h1.52
  text "PTH" at 132.308,14.921 h1.52
  text "Round" at 138.594,14.921 h1.52
  text "Top Layer - Bottom Layer" at 147.745,14.921 h1.52
  text "Pad" at 165.088,14.921 h1.52
  text "20" at 109.543,11.767 h1.52
  text "0,700mm (27,56mil)" at 117.637,11.767 h1.52
  text "PTH" at 132.308,11.767 h1.52
  text "Round" at 138.594,11.767 h1.52
  text "Top Layer - Bottom Layer" at 147.745,11.767 h1.52
  text "Pad" at 165.088,11.767 h1.52
  text "Q" at 101.741,11.513 h1.4
  text "23" at 109.543,8.613 h1.52
  text "0,900mm (35,43mil)" at 117.637,8.613 h1.52
  text "PTH" at 132.308,8.613 h1.52
  text "Round" at 138.594,8.613 h1.52
  text "Top Layer - Bottom Layer" at 147.745,8.613 h1.52
  text "Pad" at 165.088,8.613 h1.52
  text "K" at 101.741,8.359 h1.4
  text "28" at 109.543,5.458 h1.52
  text "0,400mm (15,75mil)" at 117.637,5.458 h1.52
  text "PTH" at 132.308,5.458 h1.52
  text "Round" at 138.594,5.458 h1.52
  text "Top Layer - Bottom Layer" at 147.745,5.458 h1.52
  text "Pad" at 165.088,5.458 h1.52
  text "203" at 109.543,2.304 h1.52
  text "0,200mm (7,87mil)" at 117.637,2.304 h1.52
  text "PTH" at 132.308,2.304 h1.52
  text "Round" at 138.594,2.304 h1.52
  text "Top Layer - Bottom Layer" at 147.745,2.304 h1.52
  text "Via" at 165.088,2.304 h1.52
  text "748" at 109.543,-0.85 h1.52
  text "0,350mm (13,78mil)" at 117.637,-0.85 h1.52
  text "PTH" at 132.308,-0.85 h1.52
  text "Round" at 138.594,-0.85 h1.52
  text "Top Layer - Bottom Layer" at 147.745,-0.85 h1.52
  text "Via" at 165.088,-0.85 h1.52
  text "L" at 101.741,-1.104 h1.4
  text "1085 Total" at 109.543,-4.004 h1.52
  text "Slot definitions :" at 102.383,-6.212 h1.52
  text "Routed Path Length" at 112.777,-6.212 h1.52
  text "= Calculated from tool start centre position to tool end centre position." at 125.654,-6.212 h1.52
  text "Hole Length" at 112.777,-7.474 h1.52
  text "= Routed Path Length + Tool Size = Slot length as defined in the PCB layout" at 120.873,-7.474 h1.52
  text ".Layer_Name" at -1.072,-25.883 h3
  text ".DRL" at 40.623,-25.883 h3
M20-Top Title Box:
  circle w0.254: c76.933,-32.604 r1.3
  region: 76.458,-25.367 60.931,-25.367 60.236,-27.143 59.026,-28.368 57.629,-26.508 57.629,-24.857 58.772,-23.46 60.208,-23.081 76.458,-23.081
  region: 62.455,-33.697 51.699,-33.697 52.692,-31.204 60.55,-31.204 60.998,-30.445 63.207,-32.993
  lines w0.254: 52.692,-31.204 61.484,-31.204 58.418,-27.666 cw(c60.221,-25.722) 60.462,-23.081 77.226,-23.081 76.464,-25.367 ; 56.006,-22.834 cw(c58.432,-23.805) 58.668,-21.202 ; 56.045,-22.802 51.699,-33.697 71.021,-33.697 ccw(c71.27,-30.962) 73.819,-31.982 ; 57.785,-26.736 63.207,-32.993 ; 58.039,-26.736 63.344,-32.858 ; 58.039,-26.482 63.344,-32.604 ; 58.137,-25.367 71.13,-25.367 ; 58.166,-26.355 63.471,-32.477 ; 58.293,-26.228 63.598,-32.35 ; 58.42,-26.101 63.725,-32.223 ; 58.547,-25.974 63.852,-32.096 ; 58.601,-24.022 63.906,-30.143 ; 58.67,-21.202 78.119,-21.202 73.82,-31.98 ; 58.674,-25.847 63.924,-31.906 ; 58.674,-25.593 63.979,-31.715 ; 58.674,-25.339 63.979,-31.461 ; 58.674,-24.45 63.979,-30.572 ; 58.801,-25.212 64.106,-31.334 ; 58.801,-24.831 64.106,-30.953 ; 60.172,-31.217 ccw(c60.277,-30.682) 60.575,-30.225 ; 61.259,-25.354 ccw(c61.233,-25.921) 60.903,-26.383 63.267,-29.112 cw(c61.464,-31.056) 62.196,-33.604 ; 67.54,-33.493 70.429,-25.113 ; 67.762,-33.443 70.632,-25.122 ; 67.889,-33.443 70.759,-25.122 ; 68.143,-33.443 71.013,-25.122 ; 68.397,-33.443 71.267,-25.122 ; 68.651,-33.443 71.521,-25.122 ; 68.905,-33.443 71.775,-25.122 ; 69.159,-33.443 72.029,-25.122 ; 69.413,-33.443 72.283,-25.122 ; 69.667,-33.443 72.537,-25.122 ; 69.876,-33.493 72.765,-25.113 ; 72.765,-25.367 76.458,-25.367 ; 75.79,-25.365 76.552,-23.079 ; 75.956,-25.367 76.718,-23.081 ; 76.21,-25.367 76.972,-23.081
  lines w0.3: -10.072,-37.583 79.928,-37.583 79.928,-17.583 -10.072,-17.583 ; -10.072,-32.583 49.928,-32.583 ; -10.072,-27.583 49.928,-27.583 ; -10.072,-22.583 49.928,-22.583 ; -10.071,-37.583 -10.071,-17.583 ; 29.928,-37.583 29.928,-22.583 ; 49.928,-37.583 49.928,-17.583 ; 67.54,-33.493 69.876,-33.493
  text "Project: '.Board_Name'" at -9.072,-20.799 h3
  text "Layer:" at -9.071,-25.883 h3
  text "Gerber:" at 30.917,-25.883 h3
  text "Variant: '.VariantName'" at -9.072,-30.883 h3
  text "'.Board_Reference'" at 31.044,-30.883 h3
  text "R" at 76.425,-33.366 h1.52
  text "Date: '.Board_Document_Date'" at -9.072,-35.883 h3
  text "Rev: '.Board_PCB_Revision'" at 30.987,-35.883 h3
M21-Bottom Title Box:
  circle w0.254: c-6.889,-32.604 r1.3
  region: 7.589,-33.697 18.345,-33.697 17.352,-31.204 9.494,-31.204 9.045,-30.445 6.837,-32.993
  region: -6.414,-25.367 9.113,-25.367 9.807,-27.143 11.018,-28.368 12.415,-26.508 12.415,-24.857 11.272,-23.46 9.836,-23.081 -6.414,-23.081
  lines w0.254: -6.928,-23.081 -6.166,-25.367 ; -6.674,-23.081 -5.912,-25.367 ; -6.508,-23.079 -5.746,-25.365 ; -6.42,-25.367 -7.182,-23.081 9.582,-23.081 cw(c9.822,-25.722) 11.626,-27.666 8.56,-31.204 17.352,-31.204 ; -6.414,-25.367 -2.722,-25.367 ; -3.776,-31.98 -8.076,-21.202 11.374,-21.202 ; -3.775,-31.982 ccw(c-1.226,-30.962) -0.978,-33.697 18.345,-33.697 13.999,-22.802 ; -2.722,-25.113 0.168,-33.493 ; -2.493,-25.122 0.376,-33.443 ; -2.239,-25.122 0.63,-33.443 ; -1.985,-25.122 0.884,-33.443 ; -1.731,-25.122 1.138,-33.443 ; -1.477,-25.122 1.392,-33.443 ; -1.223,-25.122 1.646,-33.443 ; -1.086,-25.367 11.907,-25.367 ; -0.969,-25.122 1.9,-33.443 ; -0.715,-25.122 2.154,-33.443 ; -0.588,-25.122 2.281,-33.443 ; -0.386,-25.113 2.504,-33.493 ; 5.938,-31.334 11.243,-25.212 ; 5.938,-30.953 11.243,-24.831 ; 6.065,-31.715 11.37,-25.593 ; 6.065,-31.461 11.37,-25.339 ; 6.065,-30.572 11.37,-24.45 ; 6.12,-31.906 11.37,-25.847 ; 6.137,-30.143 11.442,-24.022 ; 6.192,-32.096 11.497,-25.974 ; 6.319,-32.223 11.624,-26.101 ; 6.446,-32.35 11.751,-26.228 ; 6.573,-32.477 11.878,-26.355 ; 6.7,-32.858 12.005,-26.736 ; 6.7,-32.604 12.005,-26.482 ; 6.837,-32.993 12.259,-26.736 ; 7.847,-33.604 cw(c8.58,-31.056) 6.776,-29.112 9.141,-26.383 ccw(c8.811,-25.921) 8.785,-25.354 ; 9.469,-30.225 ccw(c9.766,-30.682) 9.871,-31.217 ; 11.375,-21.202 cw(c11.612,-23.805) 14.038,-22.834
  lines w0.3: 0.168,-33.493 2.504,-33.493 ; 19.928,-37.583 19.928,-17.583 ; 19.928,-32.583 79.928,-32.583 ; 19.928,-27.583 79.928,-27.583 ; 19.928,-22.583 79.928,-22.583 ; 39.928,-37.583 39.928,-22.583 ; -10.072,-37.583 79.928,-37.583 79.928,-17.583 -10.072,-17.583 -10.072,-37.583
  text "Project: '.Board_Name'" at 78.734,-20.799 h3
  text "Gerber:" at 38.745,-25.883 h3
  text "Layer:" at 78.734,-25.883 h3
  text "'.Board_Reference'" at 38.745,-30.883 h3
  text "Variant: '.VariantName'" at 78.734,-30.883 h3
  text "R" at -6.381,-33.366 h1.52
  text "Rev: '.Board_PCB_Revision'" at 38.802,-35.883 h3
  text "Date: '.Board_Document_Date'" at 78.734,-35.883 h3

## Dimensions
3,0 to 3,105 on M2-Board Dimensions
0,102 to 78,102 on M2-Board Dimensions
